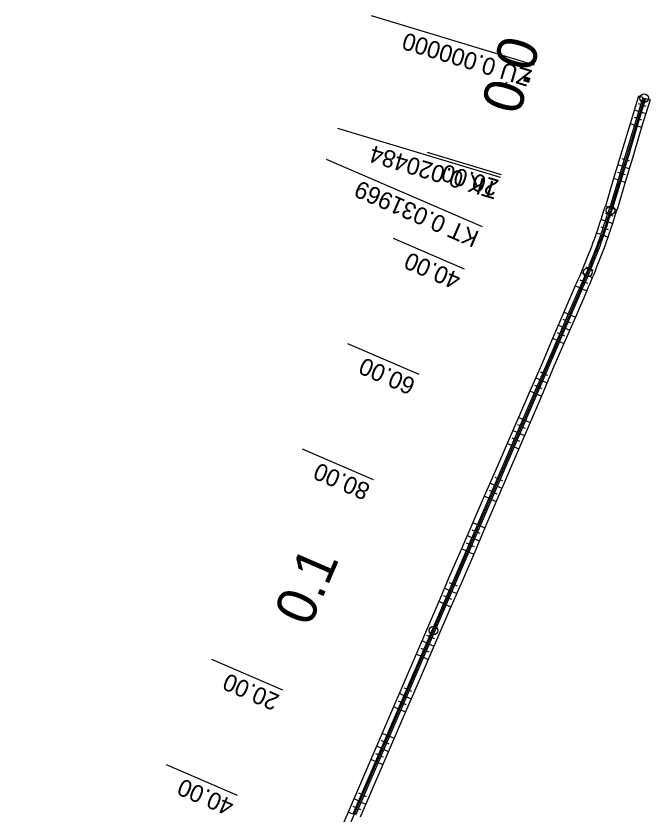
# Model space of a CAD drawing. Extents: x -481685 to -479315, y -1112639 to -1112242.
# Drawn here: x -480619.6 to -480509, y -1112497.2 to -1112357.9 of the extents above; entities that cross this region are included whole.
import ezdxf

# ---------------------------------------------------------------- set-up
doc = ezdxf.new("R2010")
doc.units = 0
for name, color, linetype in [('O6_HATCH_SLOPE_L', 7, 'Continuous'), ('O6_HATCH_SLOPE_R', 7, 'Continuous'), ('O6_HECTOMETRY', 7, 'Continuous'), ('O6_HLBODY', 7, 'Continuous'), ('O6_HRANA_TELESO', 7, 'Continuous'), ('O6_OSA', 7, 'Continuous'), ('O6_STANICENI', 7, 'Continuous'), ('O6_VOZOVKA', 7, 'Continuous'), ('O6_ZPEVKRAJ', 7, 'Continuous')]:
    doc.layers.add(name, color=color, linetype=linetype)

msp = doc.modelspace()

# ---------------------------------------------------------------- linework, layer by layer
at = {"layer": 'O6_HATCH_SLOPE_L'}
for p, q in [((-480509.73, -1112372.32), (-480508.96, -1112372.56)), ((-480510.09, -1112373.52), (-480509.71, -1112373.64)), ((-480510.81, -1112375.92), (-480510.43, -1112376.03)), ((-480510.45, -1112374.72), (-480509.69, -1112374.95)), ((-480511.17, -1112377.11), (-480510.42, -1112377.34)), ((-480513.33, -1112384.29), (-480512.58, -1112384.52)), ((-480512.97, -1112383.1), (-480512.6, -1112383.21)), ((-480512.22, -1112383.32), (-480512.22, -1112383.32)), ((-480513.69, -1112385.49), (-480513.31, -1112385.61)), ((-480512.93, -1112385.72), (-480512.93, -1112385.72)), ((-480514.05, -1112386.69), (-480513.29, -1112386.92)), ((-480515.86, -1112392.67), (-480515.47, -1112392.79)), ((-480516.24, -1112393.87), (-480515.47, -1112394.12)), ((-480515.09, -1112392.91), (-480515.09, -1112392.91)), ((-480516.63, -1112395.06), (-480516.24, -1112395.19)), ((-480515.86, -1112395.32), (-480515.86, -1112395.32)), ((-480517.04, -1112396.25), (-480516.27, -1112396.52)), ((-480519.29, -1112402.09), (-480518.91, -1112402.25)), ((-480518.53, -1112402.41), (-480518.53, -1112402.41)), ((-480519.79, -1112403.24), (-480519.03, -1112403.57)), ((-480520.28, -1112404.39), (-480519.9, -1112404.55)), ((-480519.52, -1112404.72), (-480519.52, -1112404.72)), ((-480520.78, -1112405.53), (-480520.01, -1112405.86)), ((-480523.25, -1112411.27), (-480522.87, -1112411.44)), ((-480522.48, -1112411.61), (-480522.48, -1112411.61)), ((-480524.24, -1112413.57), (-480523.86, -1112413.73)), ((-480523.75, -1112412.42), (-480522.98, -1112412.75)), ((-480524.74, -1112414.72), (-480523.98, -1112415.04)), ((-480523.48, -1112413.9), (-480523.48, -1112413.9)), ((-480527.21, -1112420.46), (-480526.84, -1112420.62)), ((-480527.71, -1112421.6), (-480526.95, -1112421.93)), ((-480526.46, -1112420.78), (-480526.46, -1112420.78)), ((-480528.2, -1112422.75), (-480527.82, -1112422.92)), ((-480527.44, -1112423.08), (-480527.44, -1112423.08)), ((-480528.7, -1112423.9), (-480527.93, -1112424.23)), ((-480531.17, -1112429.64), (-480530.78, -1112429.81)), ((-480530.39, -1112429.98), (-480530.39, -1112429.98)), ((-480531.67, -1112430.79), (-480530.88, -1112431.13)), ((-480532.66, -1112433.08), (-480531.86, -1112433.42)), ((-480532.16, -1112431.93), (-480531.77, -1112432.1)), ((-480531.37, -1112432.27), (-480531.37, -1112432.27)), ((-480535.63, -1112439.97), (-480534.82, -1112440.32)), ((-480535.13, -1112438.82), (-480534.73, -1112439)), ((-480534.32, -1112439.17), (-480534.32, -1112439.17)), ((-480536.12, -1112441.12), (-480535.72, -1112441.29)), ((-480536.62, -1112442.26), (-480535.8, -1112442.62)), ((-480535.31, -1112441.47), (-480535.31, -1112441.47)), ((-480539.1, -1112448), (-480538.68, -1112448.18)), ((-480538.26, -1112448.36), (-480538.26, -1112448.36)), ((-480539.59, -1112449.15), (-480538.75, -1112449.51)), ((-480540.09, -1112450.3), (-480539.66, -1112450.48)), ((-480539.24, -1112450.66), (-480539.24, -1112450.66)), ((-480540.58, -1112451.45), (-480539.73, -1112451.81)), ((-480543.05, -1112457.19), (-480542.64, -1112457.37)), ((-480542.22, -1112457.55), (-480542.22, -1112457.55)), ((-480544.04, -1112459.48), (-480543.63, -1112459.66)), ((-480543.55, -1112458.33), (-480542.71, -1112458.69)), ((-480544.54, -1112460.63), (-480543.71, -1112460.99)), ((-480543.21, -1112459.84), (-480543.21, -1112459.84)), ((-480547.02, -1112466.37), (-480546.6, -1112466.55)), ((-480547.51, -1112467.52), (-480546.68, -1112467.87)), ((-480546.19, -1112466.73), (-480546.19, -1112466.73)), ((-480548.01, -1112468.66), (-480547.59, -1112468.84)), ((-480547.18, -1112469.02), (-480547.18, -1112469.02)), ((-480548.5, -1112469.81), (-480547.68, -1112470.17)), ((-480550.98, -1112475.55), (-480550.57, -1112475.73)), ((-480550.16, -1112475.9), (-480550.16, -1112475.9)), ((-480551.47, -1112476.7), (-480550.66, -1112477.05)), ((-480552.46, -1112478.99), (-480551.65, -1112479.34)), ((-480551.97, -1112477.85), (-480551.56, -1112478.02)), ((-480551.15, -1112478.2), (-480551.15, -1112478.2)), ((-480555.43, -1112485.88), (-480554.63, -1112486.23)), ((-480554.94, -1112484.73), (-480554.53, -1112484.91)), ((-480554.13, -1112485.08), (-480554.13, -1112485.08)), ((-480555.93, -1112487.03), (-480555.52, -1112487.2)), ((-480555.12, -1112487.38), (-480555.12, -1112487.38)), ((-480556.42, -1112488.18), (-480555.62, -1112488.52)), ((-480558.9, -1112493.92), (-480558.49, -1112494.09)), ((-480558.09, -1112494.26), (-480558.09, -1112494.26)), ((-480559.39, -1112495.06), (-480558.58, -1112495.41)), ((-480559.89, -1112496.21), (-480559.48, -1112496.39)), ((-480559.08, -1112496.56), (-480559.08, -1112496.56))]:
    msp.add_line(p, q, dxfattribs=at)
at = {"layer": 'O6_HATCH_SLOPE_R'}
for p, q in [((-480510.23, -1112372.18), (-480511, -1112371.94)), ((-480510.95, -1112374.57), (-480511.71, -1112374.34)), ((-480510.59, -1112373.37), (-480510.97, -1112373.26)), ((-480511.31, -1112375.77), (-480511.69, -1112375.65)), ((-480511.67, -1112376.96), (-480512.42, -1112376.74)), ((-480514.22, -1112382.72), (-480514.22, -1112382.72)), ((-480513.47, -1112382.95), (-480513.85, -1112382.84)), ((-480513.83, -1112384.15), (-480514.58, -1112383.92)), ((-480514.95, -1112385.11), (-480514.95, -1112385.11)), ((-480514.19, -1112385.34), (-480514.57, -1112385.23)), ((-480514.55, -1112386.54), (-480515.31, -1112386.31)), ((-480517.12, -1112392.28), (-480517.12, -1112392.28)), ((-480516.35, -1112392.52), (-480516.74, -1112392.4)), ((-480516.73, -1112393.71), (-480517.5, -1112393.46)), ((-480517.89, -1112394.64), (-480517.89, -1112394.64)), ((-480517.12, -1112394.89), (-480517.5, -1112394.76)), ((-480517.53, -1112396.07), (-480518.29, -1112395.8)), ((-480520.53, -1112401.57), (-480520.53, -1112401.57)), ((-480519.77, -1112401.89), (-480520.15, -1112401.73)), ((-480521.52, -1112403.85), (-480521.52, -1112403.85)), ((-480520.27, -1112403.03), (-480521.02, -1112402.71)), ((-480521.26, -1112405.33), (-480522.02, -1112405)), ((-480520.76, -1112404.18), (-480521.14, -1112404.02)), ((-480524.49, -1112410.74), (-480524.49, -1112410.74)), ((-480524.23, -1112412.22), (-480524.98, -1112411.89)), ((-480523.73, -1112411.07), (-480524.11, -1112410.9)), ((-480525.48, -1112413.04), (-480525.48, -1112413.04)), ((-480524.72, -1112413.36), (-480525.1, -1112413.2)), ((-480525.22, -1112414.51), (-480525.97, -1112414.19)), ((-480528.43, -1112419.93), (-480528.43, -1112419.93)), ((-480527.69, -1112420.25), (-480528.06, -1112420.09)), ((-480528.19, -1112421.4), (-480528.93, -1112421.08)), ((-480529.42, -1112422.23), (-480529.42, -1112422.23)), ((-480528.68, -1112422.55), (-480529.05, -1112422.39)), ((-480529.18, -1112423.69), (-480529.92, -1112423.37)), ((-480532.15, -1112430.58), (-480532.91, -1112430.25)), ((-480532.42, -1112429.1), (-480532.42, -1112429.1)), ((-480531.65, -1112429.43), (-480532.03, -1112429.27)), ((-480533.41, -1112431.4), (-480533.41, -1112431.4)), ((-480532.64, -1112431.73), (-480533.03, -1112431.56)), ((-480533.14, -1112432.88), (-480533.91, -1112432.54)), ((-480536.4, -1112438.27), (-480536.4, -1112438.27)), ((-480535.61, -1112438.61), (-480536.01, -1112438.44)), ((-480536.11, -1112439.76), (-480536.9, -1112439.42)), ((-480537.4, -1112440.57), (-480537.4, -1112440.57)), ((-480536.6, -1112440.91), (-480537, -1112440.74)), ((-480537.1, -1112442.06), (-480537.9, -1112441.71)), ((-480540.39, -1112447.45), (-480540.39, -1112447.45)), ((-480539.57, -1112447.8), (-480539.98, -1112447.62)), ((-480541.39, -1112449.74), (-480541.39, -1112449.74)), ((-480540.07, -1112448.95), (-480540.89, -1112448.59)), ((-480541.06, -1112451.24), (-480541.89, -1112450.88)), ((-480540.56, -1112450.09), (-480540.98, -1112449.92)), ((-480544.37, -1112456.62), (-480544.37, -1112456.62)), ((-480544.03, -1112458.13), (-480544.86, -1112457.77)), ((-480543.53, -1112456.98), (-480543.95, -1112456.8)), ((-480545.36, -1112458.92), (-480545.36, -1112458.92)), ((-480544.52, -1112459.27), (-480544.94, -1112459.09)), ((-480545.02, -1112460.42), (-480545.85, -1112460.06)), ((-480548.32, -1112465.81), (-480548.32, -1112465.81)), ((-480547.49, -1112466.16), (-480547.91, -1112465.98)), ((-480547.99, -1112467.31), (-480548.81, -1112466.95)), ((-480548.98, -1112469.61), (-480549.8, -1112469.25)), ((-480549.31, -1112468.1), (-480549.31, -1112468.1)), ((-480548.48, -1112468.46), (-480548.89, -1112468.28)), ((-480551.95, -1112476.49), (-480552.76, -1112476.14)), ((-480552.27, -1112474.99), (-480552.27, -1112474.99)), ((-480551.45, -1112475.34), (-480551.86, -1112475.17)), ((-480553.26, -1112477.29), (-480553.26, -1112477.29)), ((-480552.44, -1112477.64), (-480552.85, -1112477.46)), ((-480552.94, -1112478.79), (-480553.75, -1112478.44)), ((-480556.22, -1112484.18), (-480556.22, -1112484.18)), ((-480555.41, -1112484.53), (-480555.82, -1112484.35)), ((-480555.91, -1112485.68), (-480556.71, -1112485.33)), ((-480557.21, -1112486.48), (-480557.21, -1112486.48)), ((-480556.4, -1112486.82), (-480556.8, -1112486.65)), ((-480556.9, -1112487.97), (-480557.7, -1112487.62)), ((-480560.18, -1112493.36), (-480560.18, -1112493.36)), ((-480559.37, -1112493.71), (-480559.78, -1112493.54)), ((-480561.17, -1112495.66), (-480561.17, -1112495.66)), ((-480559.87, -1112494.86), (-480560.67, -1112494.51)), ((-480560.86, -1112497.15), (-480561.67, -1112496.8)), ((-480560.36, -1112496.01), (-480560.77, -1112495.83))]:
    msp.add_line(p, q, dxfattribs=at)
at = {"layer": 'O6_HECTOMETRY'}
for centre in [(-480509.98, -1112372.25), (-480546.76, -1112465.12)]:
    msp.add_circle(centre, 0.75, dxfattribs=at)
at = {"layer": 'O6_HLBODY'}
for p, q in [((-480529.13, -1112366.49), (-480557.57, -1112357.93)), ((-480535.04, -1112386.1), (-480563.48, -1112377.54)), ((-480538.18, -1112394.73), (-480565.45, -1112382.97))]:
    msp.add_line(p, q, dxfattribs=at)
for centre in [(-480509.98, -1112372.25), (-480515.88, -1112391.86), (-480519.82, -1112402.65)]:
    msp.add_circle(centre, 0.75, dxfattribs=at)
at = {"layer": 'O6_HRANA_TELESO'}
for p, q in [((-480511, -1112371.94), (-480512.42, -1112376.74)), ((-480508.96, -1112372.56), (-480510.42, -1112377.34)), ((-480512.42, -1112376.74), (-480513.86, -1112381.53)), ((-480510.42, -1112377.34), (-480511.86, -1112382.13)), ((-480513.86, -1112381.53), (-480515.31, -1112386.31)), ((-480511.86, -1112382.13), (-480513.29, -1112386.92)), ((-480515.31, -1112386.31), (-480516.76, -1112391.1)), ((-480513.29, -1112386.92), (-480514.72, -1112391.71)), ((-480522.02, -1112405), (-480524, -1112409.59)), ((-480520.01, -1112405.86), (-480521.98, -1112410.46)), ((-480524, -1112409.59), (-480525.97, -1112414.19)), ((-480521.98, -1112410.46), (-480523.98, -1112415.04)), ((-480525.97, -1112414.19), (-480527.93, -1112418.78)), ((-480523.98, -1112415.04), (-480525.97, -1112419.63)), ((-480527.93, -1112418.78), (-480529.92, -1112423.37)), ((-480525.97, -1112419.63), (-480527.93, -1112424.23)), ((-480529.92, -1112423.37), (-480531.92, -1112427.96)), ((-480527.93, -1112424.23), (-480529.9, -1112428.83)), ((-480531.92, -1112427.96), (-480533.91, -1112432.54)), ((-480529.9, -1112428.83), (-480531.86, -1112433.42)), ((-480533.91, -1112432.54), (-480535.9, -1112437.13)), ((-480531.86, -1112433.42), (-480533.83, -1112438.02)), ((-480535.9, -1112437.13), (-480537.9, -1112441.71)), ((-480533.83, -1112438.02), (-480535.8, -1112442.62)), ((-480537.9, -1112441.71), (-480539.89, -1112446.3)), ((-480535.8, -1112442.62), (-480537.77, -1112447.22)), ((-480539.89, -1112446.3), (-480541.89, -1112450.88)), ((-480537.77, -1112447.22), (-480539.73, -1112451.81)), ((-480541.89, -1112450.88), (-480543.88, -1112455.47)), ((-480539.73, -1112451.81), (-480541.72, -1112456.4)), ((-480543.88, -1112455.47), (-480545.85, -1112460.06)), ((-480541.72, -1112456.4), (-480543.71, -1112460.99)), ((-480545.85, -1112460.06), (-480547.83, -1112464.66)), ((-480543.71, -1112460.99), (-480545.69, -1112465.58)), ((-480547.83, -1112464.66), (-480549.8, -1112469.25)), ((-480545.69, -1112465.58), (-480547.68, -1112470.17)), ((-480549.8, -1112469.25), (-480551.77, -1112473.84)), ((-480547.68, -1112470.17), (-480549.66, -1112474.76)), ((-480551.77, -1112473.84), (-480553.75, -1112478.44)), ((-480549.66, -1112474.76), (-480551.65, -1112479.34)), ((-480553.75, -1112478.44), (-480555.72, -1112483.03)), ((-480551.65, -1112479.34), (-480553.63, -1112483.93)), ((-480555.72, -1112483.03), (-480557.7, -1112487.62)), ((-480553.63, -1112483.93), (-480555.62, -1112488.52)), ((-480557.7, -1112487.62), (-480559.68, -1112492.22)), ((-480555.62, -1112488.52), (-480557.6, -1112493.11)), ((-480559.68, -1112492.22), (-480561.67, -1112496.8)), ((-480557.6, -1112493.11), (-480559.57, -1112497.71)), ((-480561.67, -1112496.8), (-480563.66, -1112501.39))]:
    msp.add_line(p, q, dxfattribs=at)
for centre, radius, start, end in [((-480799.72, -1112301.56), 296.79, 341.4862, 342.4421), ((-480804.21, -1112301.47), 303.23, 341.7329, 342.6867), ((-480611.58, -1112362.88), 98.93, 337.6967, 340.5615), ((-480611.71, -1112363.23), 101.08, 337.9107, 340.7755), ((-480566.43, -1112383.25), 49.46, 333.9053, 339.6751), ((-480565.5, -1112383.83), 50.54, 334.1514, 339.846)]:
    msp.add_arc(centre, radius, start, end, dxfattribs=at)
at = {"layer": 'O6_OSA'}
for p, q in [((-480509.98, -1112372.25), (-480515.88, -1112391.86)), ((-480519.82, -1112402.65), (-480619.64, -1112634.1))]:
    msp.add_line(p, q, dxfattribs=at)
msp.add_arc((-480611.64, -1112363.05), 100, 336.6698, 343.2505, dxfattribs=at)
at = {"layer": 'O6_STANICENI'}
for p, q in [((-480534.9, -1112385.64), (-480547.82, -1112381.75)), ((-480516.7, -1112391.11), (-480514.79, -1112391.69)), ((-480541.36, -1112402.1), (-480553.76, -1112396.76)), ((-480523.92, -1112409.63), (-480522.08, -1112410.42)), ((-480549.28, -1112420.47), (-480561.68, -1112415.12)), ((-480531.84, -1112427.99), (-480530, -1112428.78)), ((-480557.2, -1112438.83), (-480569.6, -1112433.49)), ((-480539.76, -1112446.36), (-480537.92, -1112447.15)), ((-480573.04, -1112475.56), (-480585.44, -1112470.22)), ((-480555.6, -1112483.09), (-480553.76, -1112483.88)), ((-480580.97, -1112493.93), (-480593.36, -1112488.58))]:
    msp.add_line(p, q, dxfattribs=at)
at = {"layer": 'O6_VOZOVKA'}
for p, q in [((-480510.22, -1112372.18), (-480511.66, -1112376.97)), ((-480509.74, -1112372.32), (-480511.18, -1112377.11)), ((-480511.66, -1112376.97), (-480513.1, -1112381.75)), ((-480511.18, -1112377.11), (-480512.62, -1112381.9)), ((-480513.1, -1112381.75), (-480514.54, -1112386.54)), ((-480512.62, -1112381.9), (-480514.06, -1112386.69)), ((-480514.54, -1112386.54), (-480515.98, -1112391.33)), ((-480514.06, -1112386.69), (-480515.5, -1112391.47)), ((-480521.25, -1112405.33), (-480523.23, -1112409.92)), ((-480520.79, -1112405.53), (-480522.77, -1112410.12)), ((-480523.23, -1112409.92), (-480525.21, -1112414.52)), ((-480522.77, -1112410.12), (-480524.75, -1112414.71)), ((-480525.21, -1112414.52), (-480527.19, -1112419.11)), ((-480524.75, -1112414.71), (-480526.73, -1112419.3)), ((-480527.19, -1112419.11), (-480529.17, -1112423.7)), ((-480526.73, -1112419.3), (-480528.71, -1112423.9)), ((-480529.17, -1112423.7), (-480531.15, -1112428.29)), ((-480528.71, -1112423.9), (-480530.69, -1112428.49)), ((-480531.15, -1112428.29), (-480533.13, -1112432.88)), ((-480530.69, -1112428.49), (-480532.67, -1112433.08)), ((-480533.13, -1112432.88), (-480535.11, -1112437.47)), ((-480532.67, -1112433.08), (-480534.65, -1112437.67)), ((-480535.11, -1112437.47), (-480537.09, -1112442.06)), ((-480534.65, -1112437.67), (-480536.63, -1112442.26)), ((-480537.09, -1112442.06), (-480539.07, -1112446.65)), ((-480536.63, -1112442.26), (-480538.61, -1112446.85)), ((-480539.07, -1112446.65), (-480541.05, -1112451.25)), ((-480538.61, -1112446.85), (-480540.59, -1112451.44)), ((-480541.05, -1112451.25), (-480543.03, -1112455.84)), ((-480540.59, -1112451.44), (-480542.57, -1112456.03)), ((-480543.03, -1112455.84), (-480545.01, -1112460.43)), ((-480542.57, -1112456.03), (-480544.55, -1112460.62)), ((-480545.01, -1112460.43), (-480546.99, -1112465.02)), ((-480544.55, -1112460.62), (-480546.53, -1112465.22)), ((-480546.99, -1112465.02), (-480548.97, -1112469.61)), ((-480546.53, -1112465.22), (-480548.51, -1112469.81)), ((-480548.97, -1112469.61), (-480550.95, -1112474.2)), ((-480548.51, -1112469.81), (-480550.49, -1112474.4)), ((-480550.95, -1112474.2), (-480552.93, -1112478.79)), ((-480550.49, -1112474.4), (-480552.47, -1112478.99)), ((-480552.93, -1112478.79), (-480554.91, -1112483.38)), ((-480552.47, -1112478.99), (-480554.45, -1112483.58)), ((-480554.91, -1112483.38), (-480556.89, -1112487.97)), ((-480554.45, -1112483.58), (-480556.43, -1112488.17)), ((-480556.89, -1112487.97), (-480558.87, -1112492.56)), ((-480556.43, -1112488.17), (-480558.41, -1112492.76)), ((-480558.87, -1112492.56), (-480560.85, -1112497.16)), ((-480558.41, -1112492.76), (-480560.39, -1112497.35))]:
    msp.add_line(p, q, dxfattribs=at)
for centre, radius, start, end in [((-480801.48, -1112301.64), 299.25, 341.6047, 342.5598), ((-480802.43, -1112301.33), 300.75, 341.6044, 342.559), ((-480611.64, -1112363.05), 99.75, 337.7982, 340.663), ((-480611.64, -1112363.05), 100.25, 337.7982, 340.663), ((-480566.08, -1112383.49), 49.88, 334.0214, 339.762), ((-480565.85, -1112383.58), 50.12, 334.0308, 339.754)]:
    msp.add_arc(centre, radius, start, end, dxfattribs=at)
at = {"layer": 'O6_ZPEVKRAJ'}
for p, q in [((-480510.22, -1112372.18), (-480511.66, -1112376.97)), ((-480509.74, -1112372.32), (-480511.18, -1112377.11)), ((-480511.66, -1112376.97), (-480513.1, -1112381.75)), ((-480511.18, -1112377.11), (-480512.62, -1112381.9)), ((-480513.1, -1112381.75), (-480514.54, -1112386.54)), ((-480512.62, -1112381.9), (-480514.06, -1112386.69)), ((-480514.54, -1112386.54), (-480515.98, -1112391.33)), ((-480514.06, -1112386.69), (-480515.5, -1112391.47)), ((-480521.25, -1112405.33), (-480523.23, -1112409.92)), ((-480520.79, -1112405.53), (-480522.77, -1112410.12)), ((-480523.23, -1112409.92), (-480525.21, -1112414.52)), ((-480522.77, -1112410.12), (-480524.75, -1112414.71)), ((-480525.21, -1112414.52), (-480527.19, -1112419.11)), ((-480524.75, -1112414.71), (-480526.73, -1112419.3)), ((-480527.19, -1112419.11), (-480529.17, -1112423.7)), ((-480526.73, -1112419.3), (-480528.71, -1112423.9)), ((-480529.17, -1112423.7), (-480531.15, -1112428.29)), ((-480528.71, -1112423.9), (-480530.69, -1112428.49)), ((-480531.15, -1112428.29), (-480533.13, -1112432.88)), ((-480530.69, -1112428.49), (-480532.67, -1112433.08)), ((-480533.13, -1112432.88), (-480535.11, -1112437.47)), ((-480532.67, -1112433.08), (-480534.65, -1112437.67)), ((-480535.11, -1112437.47), (-480537.09, -1112442.06)), ((-480534.65, -1112437.67), (-480536.63, -1112442.26)), ((-480537.09, -1112442.06), (-480539.07, -1112446.65)), ((-480536.63, -1112442.26), (-480538.61, -1112446.85)), ((-480539.07, -1112446.65), (-480541.05, -1112451.25)), ((-480538.61, -1112446.85), (-480540.59, -1112451.44)), ((-480541.05, -1112451.25), (-480543.03, -1112455.84)), ((-480540.59, -1112451.44), (-480542.57, -1112456.03)), ((-480543.03, -1112455.84), (-480545.01, -1112460.43)), ((-480542.57, -1112456.03), (-480544.55, -1112460.62)), ((-480545.01, -1112460.43), (-480546.99, -1112465.02)), ((-480544.55, -1112460.62), (-480546.53, -1112465.22)), ((-480546.99, -1112465.02), (-480548.97, -1112469.61)), ((-480546.53, -1112465.22), (-480548.51, -1112469.81)), ((-480548.97, -1112469.61), (-480550.95, -1112474.2)), ((-480548.51, -1112469.81), (-480550.49, -1112474.4)), ((-480550.95, -1112474.2), (-480552.93, -1112478.79)), ((-480550.49, -1112474.4), (-480552.47, -1112478.99)), ((-480552.93, -1112478.79), (-480554.91, -1112483.38)), ((-480552.47, -1112478.99), (-480554.45, -1112483.58)), ((-480554.91, -1112483.38), (-480556.89, -1112487.97)), ((-480554.45, -1112483.58), (-480556.43, -1112488.17)), ((-480556.89, -1112487.97), (-480558.87, -1112492.56)), ((-480556.43, -1112488.17), (-480558.41, -1112492.76)), ((-480558.87, -1112492.56), (-480560.85, -1112497.16)), ((-480558.41, -1112492.76), (-480560.39, -1112497.35))]:
    msp.add_line(p, q, dxfattribs=at)
for centre, radius, start, end in [((-480801.48, -1112301.64), 299.25, 341.6047, 342.5598), ((-480802.43, -1112301.33), 300.75, 341.6044, 342.559), ((-480611.64, -1112363.05), 99.75, 337.7982, 340.663), ((-480611.64, -1112363.05), 100.25, 337.7982, 340.663), ((-480566.08, -1112383.49), 49.88, 334.0214, 339.762), ((-480565.85, -1112383.58), 50.12, 334.0308, 339.754)]:
    msp.add_arc(centre, radius, start, end, dxfattribs=at)

# ---------------------------------------------------------------- texts
at = {"layer": 'O6_HECTOMETRY'}
for s, rotation, p in [('0.0', 73.2049, (-480531.82, -1112375.41)), ('0.1', 66.6242, (-480568.36, -1112464.69))]:
    msp.add_text(s, height=7, rotation=rotation, dxfattribs=at).set_placement(p)
at = {"layer": 'O6_HLBODY'}
for s, height, rotation, p in [('ZÚ 0.000000', 2.999, 163.2505, (-480529.42, -1112367.44)), ('TK 0.020484', 3, 163.2505, (-480535.32, -1112387.06)), ('KT 0.031969', 3, 156.6698, (-480538.58, -1112395.65))]:
    msp.add_text(s, height=height, rotation=rotation, dxfattribs=at).set_placement(p)
at = {"layer": 'O6_STANICENI'}
for s, rotation, p in [('20.00', 163.2505, (-480535.18, -1112386.6)), ('40.00', 156.6698, (-480541.76, -1112403.02)), ('60.00', 156.6698, (-480549.68, -1112421.39)), ('80.00', 156.6698, (-480557.6, -1112439.75)), ('20.00', 156.6698, (-480573.44, -1112476.48)), ('40.00', 156.6698, (-480581.36, -1112494.84))]:
    msp.add_text(s, height=2.999, rotation=rotation, dxfattribs=at).set_placement(p)

doc.saveas('drawing.dxf')
